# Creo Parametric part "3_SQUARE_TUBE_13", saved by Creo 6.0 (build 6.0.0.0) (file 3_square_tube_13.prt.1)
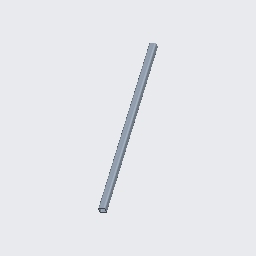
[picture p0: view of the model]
Units: Custom; MM, KILOGRAM, SECS
Materials in the file: STEEL

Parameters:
  BUW_NAME = "SQUARE TUBE"
  BUW_TYPE = "DIN EN 10219"
  BUW_SIZE = "25x25x3.0"
  BUW_LENGTH_STR = "680"
  PTC_MATERIAL_NAME = "STEEL"
  BUW_PROFIL_TYPE = "square_tube"
  BUW_PROFILE_PATH = "parts//profiles/steel_beams_mm/"
  BUW_PROFILE_NAME_LANG = "SQUARE TUBE"
  BUW_TAB_SEL_INFO = "-2 TYPE DIN_EN_10219-1997 SIZE_DINEN_10219 25x25x3.0"
  NAMING = "SQUARE TUBE"
  DESIGNATION = "DIN EN 10219 25x25x3.0 x 680"
  PROFIL_RASTER_POS = "X_0"
  BUW_OBJECT_ROLE = "PROFIL_SYSTEM_BORE_END_POINTS"
  PRO_UNIT_SYS = "Custom"

Other parameters: BUW_LENGTH, LENGTH, BUW_LENGTH_Z_MIN_PARAM, D8, D93, D94, d26, d8, d93, d94, d98, D98, SHEAR_MODULUS, THERM_EXPANSION_REF_TEMPERATURE, STRUCTURAL_DAMPING_COEFFICIENT, STRESS_LIMIT_FOR_TENSION, STRESS_LIMIT_FOR_COMPRESSION, STRESS_LIMIT_FOR_SHEAR, EMISSIVITY

Created from: SQUARE_TUBE.PRT

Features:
  1. datum plane "YZ"
  2. datum plane "XZ"
  3. datum plane "XY"
  4. coordinate system
  5. coordinate system
  6. coordinate system
  7. coordinate system
  8. datum plane "DTM3"
  9. datum plane "DTM4"
  10. datum plane "DTM5"
  11. protrusion
  12. round
  13. round
  14. datum axis
  15. datum point "PNT0"
  16. datum point

Other named items: PROFIL_CUT_QUILT, PROFILE_LENGTH_DIM, CONTACT_SURF_3, CONTACT_SURF_2, CONTACT_SURF_1, CONTACT_SURF_0, E, START_SURFACE, END_SURFACE, SIDE_SURF_3, SIDE_SURF_0, SIDE_SURF_1, SIDE_SURF_2, EDGE_7_S, EDGE_7_E, EDGE_1_S, EDGE_1_E, EDGE_3_S, EDGE_3_E, EDGE_5_S, EDGE_5_E, EDGE_6_S, EDGE_4_S, EDGE_2_S, EDGE_0_S, EDGE_6_E, EDGE_4_E, EDGE_2_E, EDGE_0_E, CS0, CS_S, CS_E, CS3

Named dimensions: X_ROT_S, Y_ROT_S, Z_OFF_S, X_ROT_E, Y_ROT_E, Z_OFF_E, PC_L, BUW_LENGTH_Z_MIN, BUW_LENGTH_DIM

Layers: 00_PROFIL_DATUM, 00_PROFIL_DRW_HIDE, 00_PROFIL_END_CSYS, 00_PROFIL_GEOMETRY, 00_PROFIL_QUILT, 00_PROFIL_SIZE_NOTE

Surfaces: 16 plane, 12 cylinder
